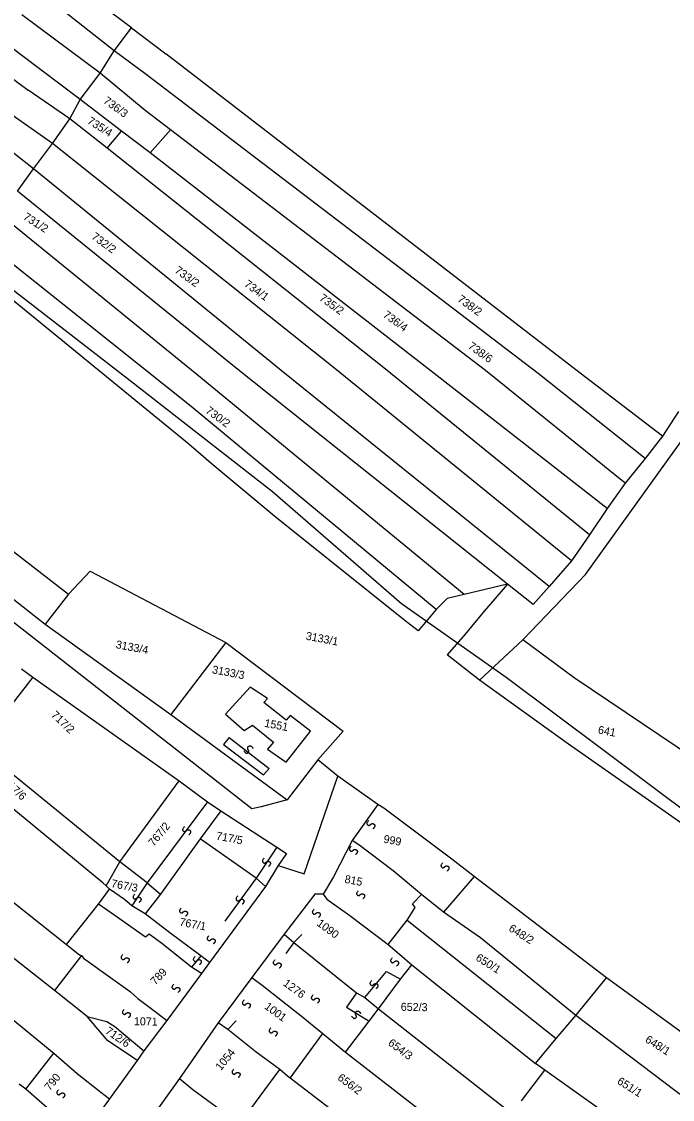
# Model space of a CAD drawing. Extents: x -581999 to -572728, y -1219553 to -1212032.
# Drawn here: x -577691.9 to -577529.2, y -1214814.1 to -1214544.8 of the extents above; entities that cross this region are included whole.
import ezdxf

# ---------------------------------------------------------------- set-up
doc = ezdxf.new("R2010")
doc.units = 0
for name, color, linetype in [('Vrstva 1', 7, 'Continuous'), ('Vrstva 2', 7, 'Continuous'), ('Vrstva 4', 7, 'Continuous'), ('Vrstva 6', 7, 'Continuous'), ('Vrstva 63', 7, 'Continuous')]:
    doc.layers.add(name, color=color, linetype=linetype)

msp = doc.modelspace()

# ---------------------------------------------------------------- linework, layer by layer
at = {"layer": 'Vrstva 1'}
for p, q in [((-577670.52, -1214576.417), (-577666.943, -1214572.148)), ((-577659.788, -1214577.612), (-577654.678, -1214571.806)), ((-577570.401, -1214685.384), (-577637.831, -1214631.7)), ((-577581.241, -1214687.954), (-577648.09, -1214633.013)), ((-577588.268, -1214691.703), (-577649.503, -1214641.002)), ((-577596.47, -1214694.225), (-577628.644, -1214668.451)), ((-577570.401, -1214685.384), (-577576.254, -1214692.158)), ((-577563.988, -1214690.489), (-577570.401, -1214685.384)), ((-577560.027, -1214685.925), (-577563.988, -1214690.489)), ((-577585.548, -1214688.977), (-577588.268, -1214691.703)), ((-577588.268, -1214691.703), (-577592.801, -1214697.043)), ((-577576.254, -1214692.158), (-577581.014, -1214697.839)), ((-577592.801, -1214697.043), (-577596.47, -1214694.225)), ((-577581.014, -1214697.839), (-577585.548, -1214703.065)), ((-577640.848, -1214699.921), (-577654.641, -1214717.954)), ((-577577.468, -1214709.362), (-577585.548, -1214703.065)), ((-577602.862, -1214740.427), (-577609.295, -1214749.455)), ((-577609.295, -1214749.455), (-577613.926, -1214758.483)), ((-577607.627, -1214750.552), (-577609.295, -1214749.455)), ((-577660.529, -1214760.031), (-577657.2, -1214762.813)), ((-577515.871, -1214821.604), (-577553.393, -1214793.129))]:
    msp.add_line(p, q, dxfattribs=at)
for points in [[(-577691.898, -1214553.29), (-577803.409, -1214468.543)], [(-577811.723, -1214471.875), (-577690.317, -1214561.946)], [(-577668.805, -1214552.092), (-577691.822, -1214533.865)], [(-577664.441, -1214546.324), (-577680.573, -1214534.167)], [(-577672.289, -1214557.707), (-577691.858, -1214543.078)], [(-577668.805, -1214552.092), (-577664.441, -1214546.324)], [(-577664.441, -1214546.324), (-577655.83, -1214552.859)], [(-577677.248, -1214564.27), (-577691.898, -1214553.29)], [(-577672.289, -1214557.707), (-577668.805, -1214552.092)], [(-577660.784, -1214558.021), (-577668.805, -1214552.092)], [(-577552.295, -1214632.621), (-577655.83, -1214552.859)], [(-577688.959, -1214581.583), (-577718.278, -1214558.503)], [(-577677.248, -1214564.27), (-577672.289, -1214557.707)], [(-577661.018, -1214567.027), (-577672.289, -1214557.707)], [(-577562.738, -1214632.734), (-577660.784, -1214558.021)], [(-577650.134, -1214650.396), (-577757.585, -1214562.563)], [(-577684.199, -1214575.219), (-577702.752, -1214562.237)], [(-577679.833, -1214569.052), (-577690.317, -1214561.946)], [(-577679.833, -1214569.052), (-577677.248, -1214564.27)], [(-577588.749, -1214632.714), (-577659.788, -1214577.612), (-577666.943, -1214572.148), (-577677.248, -1214564.27)], [(-577575.936, -1214632.022), (-577654.678, -1214571.806), (-577661.018, -1214567.027)], [(-577684.199, -1214575.219), (-577679.833, -1214569.052)], [(-577600.965, -1214631.61), (-577670.52, -1214576.417), (-577679.833, -1214569.052)], [(-577688.959, -1214581.583), (-577684.199, -1214575.219)], [(-577613.58, -1214631.504), (-577684.199, -1214575.219)], [(-577692.928, -1214587.153), (-577688.959, -1214581.583)], [(-577626.988, -1214631.991), (-577688.959, -1214581.583)], [(-577637.831, -1214631.7), (-577692.928, -1214587.153)], [(-577648.09, -1214633.013), (-577697.095, -1214593.122)], [(-577649.503, -1214641.002), (-577701.855, -1214599.286)], [(-577554.482, -1214679.576), (-577613.58, -1214631.504)], [(-577549.922, -1214673.019), (-577600.965, -1214631.61)], [(-577631.991, -1214741.032), (-577634.339, -1214741.551), (-577714.436, -1214678.933), (-577775.891, -1214632.778)], [(-577560.027, -1214685.925), (-577626.988, -1214631.991)], [(-577545.558, -1214666.46), (-577588.749, -1214632.714)], [(-577540.998, -1214660.102), (-577575.936, -1214632.022)], [(-577566.588, -1214699.26), (-577550.953, -1214683.002), (-577514.672, -1214632.54)], [(-577536.045, -1214653.947), (-577562.738, -1214632.734)], [(-577531.686, -1214648.387), (-577552.295, -1214632.621)], [(-577527.717, -1214642.224), (-577531.686, -1214648.387)], [(-577644.639, -1214655.116), (-577650.134, -1214650.396)], [(-577531.686, -1214648.387), (-577536.045, -1214653.947)], [(-577628.644, -1214668.451), (-577644.639, -1214655.116)], [(-577536.045, -1214653.947), (-577540.998, -1214660.102)], [(-577540.998, -1214660.102), (-577545.558, -1214666.46)], [(-577545.558, -1214666.46), (-577549.922, -1214673.019)], [(-577549.922, -1214673.019), (-577554.482, -1214679.576)], [(-577554.482, -1214679.576), (-577560.027, -1214685.925)], [(-577680.179, -1214687.879), (-577674.78, -1214682.14), (-577640.848, -1214699.921), (-577611.531, -1214722.118), (-577617.879, -1214729.244)], [(-577570.401, -1214685.384), (-577581.241, -1214687.954), (-577585.548, -1214688.977)], [(-577680.179, -1214687.879), (-577686.024, -1214695.333)], [(-577686.024, -1214695.333), (-577654.641, -1214717.954), (-577625.534, -1214739.291)], [(-577577.468, -1214709.362), (-577566.588, -1214699.26)], [(-577553.766, -1214708.8), (-577566.588, -1214699.26)], [(-577691.97, -1214706.552), (-577689.107, -1214708.631)], [(-577689.107, -1214708.631), (-577652.569, -1214734.552)], [(-577443.209, -1214803.732), (-577555.221, -1214725.368), (-577577.468, -1214709.362)], [(-577437.811, -1214786.816), (-577553.766, -1214708.8)], [(-577634.744, -1214711.087), (-577640.984, -1214717.905), (-577636.296, -1214721.95), (-577634.219, -1214720.63), (-577628.969, -1214724.87), (-577630.481, -1214726.574), (-577625.79, -1214729.854), (-577619.735, -1214722.082), (-577624.8, -1214718.226), (-577625.747, -1214719.372), (-577631.4, -1214714.962), (-577630.427, -1214713.984), (-577634.744, -1214711.087)], [(-577667.372, -1214754.76), (-577702.712, -1214726.052)], [(-577670.759, -1214760.798), (-577671.614, -1214760.013), (-577706.69, -1214731.204)], [(-577617.879, -1214729.244), (-577625.534, -1214739.291)], [(-577612.872, -1214733.36), (-577617.879, -1214729.244)], [(-577627.757, -1214755.657), (-577621.304, -1214757.745), (-577612.872, -1214733.36)], [(-577601.381, -1214741.367), (-577602.862, -1214740.427), (-577612.872, -1214733.36)], [(-577667.372, -1214754.76), (-577652.569, -1214734.552)], [(-577652.569, -1214734.552), (-577645.456, -1214739.736)], [(-577625.534, -1214739.291), (-577631.991, -1214741.032)], [(-577642.085, -1214742.015), (-577647.261, -1214749.052)], [(-577645.456, -1214739.736), (-577642.085, -1214742.015)], [(-577642.085, -1214742.015), (-577628.128, -1214751.096)], [(-577584.347, -1214754.125), (-577601.381, -1214741.367)], [(-577720.599, -1214743.762), (-577680.664, -1214775.408)], [(-577647.261, -1214749.052), (-577657.2, -1214762.813), (-577660.988, -1214767.785)], [(-577633.306, -1214758.865), (-577647.261, -1214749.052)], [(-577683.655, -1214786.955), (-577727.473, -1214752.486)], [(-577628.128, -1214751.096), (-577625.697, -1214752.671)], [(-577625.697, -1214752.671), (-577627.757, -1214755.657)], [(-577599.014, -1214757.022), (-577607.627, -1214750.552)], [(-577670.759, -1214760.798), (-577667.372, -1214754.76)], [(-577660.529, -1214760.031), (-577667.372, -1214754.76)], [(-577627.757, -1214755.657), (-577630.962, -1214760.92)], [(-577578.749, -1214758.393), (-577584.347, -1214754.125)], [(-577613.926, -1214758.483), (-577616.515, -1214762.83)], [(-577591.952, -1214762.918), (-577599.014, -1214757.022)], [(-577578.749, -1214758.393), (-577586.433, -1214767.341)], [(-577545.717, -1214783.726), (-577578.749, -1214758.393)], [(-577669.904, -1214761.582), (-577670.759, -1214760.798)], [(-577630.962, -1214760.92), (-577644.946, -1214779.941)], [(-577630.962, -1214760.92), (-577633.306, -1214758.865)], [(-577734.351, -1214761.263), (-577683.898, -1214802.605)], [(-577672.719, -1214765.351), (-577669.904, -1214761.582)], [(-577666.211, -1214764.174), (-577669.904, -1214761.582)], [(-577616.515, -1214762.83), (-577618.62, -1214762.813), (-577626.308, -1214772.863)], [(-577616.515, -1214762.83), (-577615.609, -1214764.055)], [(-577594.165, -1214765.294), (-577591.952, -1214762.918)], [(-577586.433, -1214767.341), (-577591.952, -1214762.918)], [(-577680.664, -1214775.408), (-577672.719, -1214765.351)], [(-577668.846, -1214768.036), (-577672.719, -1214765.351)], [(-577664.321, -1214765.745), (-577666.211, -1214764.174)], [(-577660.988, -1214767.785), (-577664.321, -1214765.745)], [(-577615.609, -1214764.055), (-577609.866, -1214768.143)], [(-577595.512, -1214769.326), (-577593.504, -1214766.197), (-577594.165, -1214765.294)], [(-577660.921, -1214773.59), (-577668.846, -1214768.036)], [(-577654.866, -1214772.501), (-577660.988, -1214767.785)], [(-577609.866, -1214768.143), (-577600.26, -1214775.405)], [(-577553.393, -1214793.129), (-577577.221, -1214773.748), (-577586.433, -1214767.341)], [(-577600.26, -1214775.405), (-577595.512, -1214769.326)], [(-577595.512, -1214769.326), (-577558.285, -1214798.909)], [(-577656.863, -1214775.177), (-577660.015, -1214772.865), (-577660.921, -1214773.59)], [(-577647.124, -1214778.236), (-577654.866, -1214772.501)], [(-577626.308, -1214772.863), (-577634.388, -1214783.632)], [(-577626.308, -1214772.863), (-577623.882, -1214774.944)], [(-577680.664, -1214775.408), (-577677.423, -1214777.996), (-577676.966, -1214778.171)], [(-577649.483, -1214781.092), (-577656.863, -1214775.177)], [(-577623.882, -1214774.944), (-577608.205, -1214787.531)], [(-577600.26, -1214775.405), (-577597.441, -1214777.801), (-577594.337, -1214780.504)], [(-577676.966, -1214778.171), (-577683.655, -1214786.955)], [(-577676.966, -1214778.171), (-577676.432, -1214778.827), (-577669.092, -1214784.053)], [(-577644.946, -1214779.941), (-577647.124, -1214778.236)], [(-577644.946, -1214779.941), (-577646.944, -1214782.672)], [(-577646.944, -1214782.672), (-577655.636, -1214794.441)], [(-577646.944, -1214782.672), (-577649.483, -1214781.092)], [(-577597.188, -1214784.103), (-577594.337, -1214780.504)], [(-577594.337, -1214780.504), (-577563.407, -1214805.156)], [(-577669.092, -1214784.053), (-577665.4, -1214786.736)], [(-577634.388, -1214783.632), (-577642.746, -1214795.023)], [(-577634.388, -1214783.632), (-577631.777, -1214785.626)], [(-577602.684, -1214791.504), (-577597.188, -1214784.103)], [(-577553.393, -1214793.129), (-577545.717, -1214783.726)], [(-577392.981, -1214894.666), (-577446.519, -1214855.132), (-577501.431, -1214815.879), (-577545.717, -1214783.726)], [(-577675.552, -1214793.424), (-577683.655, -1214786.955)], [(-577665.4, -1214786.736), (-577664.69, -1214787.284)], [(-577664.69, -1214787.284), (-577662.88, -1214788.952)], [(-577631.777, -1214785.626), (-577621.619, -1214793.565)], [(-577608.205, -1214787.531), (-577606.105, -1214788.67)], [(-577662.88, -1214788.952), (-577657.838, -1214792.652)], [(-577606.105, -1214788.67), (-577602.684, -1214791.504)], [(-577670.339, -1214799.504), (-577675.552, -1214793.424)], [(-577675.552, -1214793.424), (-577670.591, -1214794.653)], [(-577657.838, -1214792.652), (-577655.636, -1214794.441)], [(-577604.987, -1214794.598), (-577602.684, -1214791.504)], [(-577602.684, -1214791.504), (-577569.32, -1214817.641)], [(-577558.285, -1214798.909), (-577553.393, -1214793.129)], [(-577670.591, -1214794.653), (-577668.609, -1214795.948)], [(-577668.609, -1214795.948), (-577661.356, -1214801.993)], [(-577655.636, -1214794.441), (-577661.356, -1214801.993)], [(-577642.746, -1214795.023), (-577652.443, -1214808.875)], [(-577640.354, -1214796.663), (-577642.746, -1214795.023)], [(-577621.619, -1214793.565), (-577618.749, -1214795.946)], [(-577618.749, -1214795.946), (-577616.631, -1214797.653)], [(-577610.911, -1214802.293), (-577604.987, -1214794.598)], [(-577633.287, -1214802.332), (-577640.354, -1214796.663)], [(-577624.766, -1214808.82), (-577616.631, -1214797.653)], [(-577616.631, -1214797.653), (-577616.541, -1214797.759), (-577610.911, -1214802.293)], [(-577664.935, -1214803.115), (-577670.339, -1214799.504)], [(-577563.407, -1214805.156), (-577558.285, -1214798.909)], [(-577690.887, -1214811.561), (-577683.898, -1214802.605)], [(-577683.898, -1214802.605), (-577678.047, -1214807.682)], [(-577662.991, -1214804.451), (-577664.935, -1214803.115)], [(-577661.356, -1214801.993), (-577662.991, -1214804.451)], [(-577627.323, -1214806.643), (-577633.287, -1214802.332)], [(-577610.911, -1214802.293), (-577577.009, -1214828.694)], [(-577662.991, -1214804.451), (-577669.983, -1214814.006)], [(-577637.213, -1214820.018), (-577627.323, -1214806.643)], [(-577624.766, -1214808.82), (-577625.447, -1214808.342), (-577627.323, -1214806.643)], [(-577566.929, -1214814.48), (-577561.078, -1214806.816)], [(-577561.078, -1214806.816), (-577563.407, -1214805.156)], [(-577527.934, -1214830.82), (-577532.103, -1214827.51), (-577561.078, -1214806.816)], [(-577678.047, -1214807.682), (-577672.106, -1214812.303)], [(-577652.443, -1214808.875), (-577660.874, -1214820.637)], [(-577652.443, -1214808.875), (-577649.144, -1214811.619)], [(-577584.785, -1214839.458), (-577624.766, -1214808.82)], [(-577690.887, -1214811.561), (-577692.508, -1214810.36)], [(-577684.856, -1214816.822), (-577690.887, -1214811.561)], [(-577672.106, -1214812.303), (-577669.983, -1214814.006)], [(-577649.144, -1214811.619), (-577640.086, -1214818.2)], [(-577669.983, -1214814.006), (-577676.755, -1214823.38)]]:
    msp.add_lwpolyline(points, dxfattribs=at)
at = {"layer": 'Vrstva 4'}
for points in [[(-577724.162, -1214665.361), (-577718.492, -1214658.259), (-577680.179, -1214687.879)], [(-577724.162, -1214665.361), (-577686.024, -1214695.333)], [(-577689.107, -1214708.631), (-577702.712, -1214726.052)], [(-577640.067, -1214723.676), (-577641.483, -1214725.45), (-577631.477, -1214733.028), (-577630.061, -1214731.433)], [(-577640.067, -1214723.676), (-577630.061, -1214731.433)], [(-577645.456, -1214739.736), (-577660.529, -1214760.031)], [(-577628.128, -1214751.096), (-577633.306, -1214758.865)], [(-577660.529, -1214760.031), (-577664.321, -1214765.745)], [(-577633.306, -1214758.865), (-577641.092, -1214769.611)], [(-577621.86, -1214772.9), (-577623.882, -1214774.944)], [(-577623.882, -1214774.944), (-577625.831, -1214777.636)], [(-577647.124, -1214778.236), (-577649.483, -1214781.092)], [(-577606.105, -1214788.67), (-577600.658, -1214782.14)], [(-577600.658, -1214782.14), (-577597.188, -1214784.103)], [(-577608.205, -1214787.531), (-577610.652, -1214791.098), (-577604.987, -1214794.598)], [(-577638.319, -1214794.508), (-577640.354, -1214796.663)]]:
    msp.add_lwpolyline(points, dxfattribs=at)
at = {"layer": 'Vrstva 6'}
for points in [[(-577636.336, -1214727.051), (-577635.856, -1214727.758), (-577635.162, -1214727.447), (-577635.085, -1214727.047), (-577635.321, -1214726.702), (-577635.406, -1214726.37), (-577635.324, -1214726.08), (-577635.18, -1214725.9), (-577634.944, -1214725.772), (-577634.579, -1214725.808), (-577634.152, -1214726.247), (-577634.097, -1214726.42)], [(-577605.177, -1214744.443), (-577605.764, -1214745.065), (-577605.309, -1214745.674), (-577604.903, -1214745.662), (-577604.617, -1214745.357), (-577604.311, -1214745.203), (-577604.011, -1214745.219), (-577603.804, -1214745.321), (-577603.628, -1214745.524), (-577603.583, -1214745.888), (-577603.918, -1214746.4), (-577604.076, -1214746.492)], [(-577651.235, -1214745.991), (-577651.822, -1214746.613), (-577651.367, -1214747.222), (-577650.961, -1214747.21), (-577650.675, -1214746.905), (-577650.369, -1214746.751), (-577650.069, -1214746.767), (-577649.862, -1214746.869), (-577649.686, -1214747.072), (-577649.641, -1214747.436), (-577649.976, -1214747.948), (-577650.134, -1214748.04)], [(-577609.551, -1214750.892), (-577610.138, -1214751.514), (-577609.683, -1214752.123), (-577609.277, -1214752.111), (-577608.991, -1214751.806), (-577608.685, -1214751.652), (-577608.385, -1214751.668), (-577608.178, -1214751.77), (-577608.002, -1214751.973), (-577607.957, -1214752.337), (-577608.292, -1214752.849), (-577608.45, -1214752.941)], [(-577631.292, -1214753.866), (-577631.879, -1214754.488), (-577631.424, -1214755.097), (-577631.018, -1214755.085), (-577630.732, -1214754.78), (-577630.426, -1214754.626), (-577630.126, -1214754.642), (-577629.919, -1214754.744), (-577629.743, -1214754.947), (-577629.698, -1214755.311), (-577630.033, -1214755.823), (-577630.191, -1214755.915)], [(-577586.651, -1214755.019), (-577587.238, -1214755.641), (-577586.783, -1214756.25), (-577586.377, -1214756.238), (-577586.091, -1214755.933), (-577585.785, -1214755.779), (-577585.485, -1214755.795), (-577585.278, -1214755.897), (-577585.102, -1214756.1), (-577585.057, -1214756.464), (-577585.392, -1214756.976), (-577585.55, -1214757.068)], [(-577663.641, -1214762.844), (-577664.228, -1214763.466), (-577663.773, -1214764.075), (-577663.367, -1214764.063), (-577663.081, -1214763.758), (-577662.775, -1214763.604), (-577662.475, -1214763.62), (-577662.268, -1214763.722), (-577662.092, -1214763.925), (-577662.047, -1214764.289), (-577662.382, -1214764.801), (-577662.54, -1214764.893)], [(-577637.887, -1214763.316), (-577638.474, -1214763.938), (-577638.019, -1214764.547), (-577637.613, -1214764.535), (-577637.327, -1214764.23), (-577637.021, -1214764.076), (-577636.721, -1214764.092), (-577636.514, -1214764.194), (-577636.338, -1214764.397), (-577636.293, -1214764.761), (-577636.628, -1214765.273), (-577636.786, -1214765.365)], [(-577607.75, -1214761.983), (-577608.337, -1214762.605), (-577607.882, -1214763.214), (-577607.476, -1214763.202), (-577607.19, -1214762.897), (-577606.884, -1214762.743), (-577606.584, -1214762.759), (-577606.377, -1214762.861), (-577606.201, -1214763.064), (-577606.156, -1214763.428), (-577606.491, -1214763.94), (-577606.649, -1214764.032)], [(-577652.02, -1214766.309), (-577652.607, -1214766.931), (-577652.152, -1214767.54), (-577651.746, -1214767.528), (-577651.46, -1214767.223), (-577651.154, -1214767.069), (-577650.854, -1214767.085), (-577650.647, -1214767.187), (-577650.471, -1214767.39), (-577650.426, -1214767.754), (-577650.761, -1214768.266), (-577650.919, -1214768.358)], [(-577618.814, -1214766.626), (-577619.401, -1214767.248), (-577618.946, -1214767.857), (-577618.54, -1214767.845), (-577618.254, -1214767.54), (-577617.948, -1214767.386), (-577617.648, -1214767.402), (-577617.441, -1214767.504), (-577617.265, -1214767.707), (-577617.22, -1214768.071), (-577617.555, -1214768.583), (-577617.713, -1214768.675)], [(-577645.111, -1214773.239), (-577645.698, -1214773.861), (-577645.243, -1214774.47), (-577644.837, -1214774.458), (-577644.551, -1214774.153), (-577644.245, -1214773.999), (-577643.945, -1214774.015), (-577643.738, -1214774.117), (-577643.562, -1214774.32), (-577643.517, -1214774.684), (-577643.852, -1214775.196), (-577644.01, -1214775.288)], [(-577666.625, -1214777.964), (-577667.212, -1214778.586), (-577666.757, -1214779.195), (-577666.351, -1214779.183), (-577666.065, -1214778.878), (-577665.759, -1214778.724), (-577665.459, -1214778.74), (-577665.252, -1214778.842), (-577665.076, -1214779.045), (-577665.031, -1214779.409), (-577665.366, -1214779.921), (-577665.524, -1214780.013)], [(-577648.566, -1214778.437), (-577649.153, -1214779.059), (-577648.698, -1214779.668), (-577648.292, -1214779.656), (-577648.006, -1214779.351), (-577647.7, -1214779.197), (-577647.4, -1214779.213), (-577647.193, -1214779.315), (-577647.017, -1214779.518), (-577646.972, -1214779.882), (-577647.307, -1214780.394), (-577647.465, -1214780.486)], [(-577628.592, -1214779.265), (-577629.179, -1214779.887), (-577628.724, -1214780.496), (-577628.318, -1214780.484), (-577628.032, -1214780.179), (-577627.726, -1214780.025), (-577627.426, -1214780.041), (-577627.219, -1214780.143), (-577627.043, -1214780.346), (-577626.998, -1214780.71), (-577627.333, -1214781.222), (-577627.491, -1214781.314)], [(-577599.259, -1214778.749), (-577599.846, -1214779.371), (-577599.391, -1214779.98), (-577598.985, -1214779.968), (-577598.699, -1214779.663), (-577598.393, -1214779.509), (-577598.093, -1214779.525), (-577597.886, -1214779.627), (-577597.71, -1214779.83), (-577597.665, -1214780.194), (-577598, -1214780.706), (-577598.158, -1214780.798)], [(-577653.905, -1214785.367), (-577654.492, -1214785.989), (-577654.037, -1214786.598), (-577653.631, -1214786.586), (-577653.345, -1214786.281), (-577653.039, -1214786.127), (-577652.739, -1214786.143), (-577652.532, -1214786.245), (-577652.356, -1214786.448), (-577652.311, -1214786.812), (-577652.646, -1214787.324), (-577652.804, -1214787.416)], [(-577604.405, -1214784.424), (-577604.992, -1214785.046), (-577604.537, -1214785.655), (-577604.131, -1214785.643), (-577603.845, -1214785.338), (-577603.539, -1214785.184), (-577603.239, -1214785.2), (-577603.032, -1214785.302), (-577602.856, -1214785.505), (-577602.811, -1214785.869), (-577603.146, -1214786.381), (-577603.304, -1214786.473)], [(-577619.072, -1214788.035), (-577619.659, -1214788.657), (-577619.204, -1214789.266), (-577618.798, -1214789.254), (-577618.512, -1214788.949), (-577618.206, -1214788.795), (-577617.906, -1214788.811), (-577617.699, -1214788.913), (-577617.523, -1214789.116), (-577617.478, -1214789.48), (-577617.813, -1214789.992), (-577617.971, -1214790.084)], [(-577636.311, -1214789.325), (-577636.898, -1214789.947), (-577636.443, -1214790.556), (-577636.037, -1214790.544), (-577635.751, -1214790.239), (-577635.445, -1214790.085), (-577635.145, -1214790.101), (-577634.938, -1214790.203), (-577634.762, -1214790.406), (-577634.717, -1214790.77), (-577635.052, -1214791.282), (-577635.21, -1214791.374)], [(-577666.31, -1214791.667), (-577666.897, -1214792.289), (-577666.442, -1214792.898), (-577666.036, -1214792.886), (-577665.75, -1214792.581), (-577665.444, -1214792.427), (-577665.144, -1214792.443), (-577664.937, -1214792.545), (-577664.761, -1214792.748), (-577664.716, -1214793.112), (-577665.051, -1214793.624), (-577665.209, -1214793.716)], [(-577609.422, -1214793.32), (-577608.942, -1214794.027), (-577608.248, -1214793.716), (-577608.171, -1214793.316), (-577608.407, -1214792.971), (-577608.492, -1214792.639), (-577608.41, -1214792.349), (-577608.266, -1214792.169), (-577608.03, -1214792.041), (-577607.665, -1214792.077), (-577607.238, -1214792.516), (-577607.183, -1214792.689)], [(-577629.621, -1214796.289), (-577630.208, -1214796.911), (-577629.753, -1214797.52), (-577629.347, -1214797.508), (-577629.061, -1214797.203), (-577628.755, -1214797.049), (-577628.455, -1214797.065), (-577628.248, -1214797.167), (-577628.072, -1214797.37), (-577628.027, -1214797.734), (-577628.362, -1214798.246), (-577628.52, -1214798.338)], [(-577638.884, -1214806.607), (-577639.471, -1214807.229), (-577639.016, -1214807.838), (-577638.61, -1214807.826), (-577638.324, -1214807.521), (-577638.018, -1214807.367), (-577637.718, -1214807.383), (-577637.511, -1214807.485), (-577637.335, -1214807.688), (-577637.29, -1214808.052), (-577637.625, -1214808.564), (-577637.783, -1214808.656)], [(-577682.714, -1214811.748), (-577683.301, -1214812.37), (-577682.846, -1214812.979), (-577682.44, -1214812.967), (-577682.154, -1214812.662), (-577681.848, -1214812.508), (-577681.548, -1214812.524), (-577681.341, -1214812.626), (-577681.165, -1214812.829), (-577681.12, -1214813.193), (-577681.455, -1214813.705), (-577681.613, -1214813.797)]]:
    msp.add_open_spline(points, degree=2, dxfattribs=at)
at = {"layer": 'Vrstva 63'}
for p, q in [((-577665.568, -1214634.018), (-577712.533, -1214597.644)), ((-577629.214, -1214662.33), (-577665.568, -1214634.018)), ((-577596.927, -1214690.291), (-577629.214, -1214662.33)), ((-577570.753, -1214708.731), (-577596.927, -1214690.291)), ((-577499.295, -1214762.226), (-577570.753, -1214708.731))]:
    msp.add_line(p, q, dxfattribs=at)

# ---------------------------------------------------------------- texts
at = {"layer": 'Vrstva 2'}
for s, rotation, p in [('736/3', 324.12454, (-577671.657, -1214564.967)), ('735/4', 327.58282, (-577675.688, -1214570.092)), ('731/2', 327.58282, (-577691.705, -1214594.067)), ('732/2', 324.12454, (-577674.626, -1214598.915)), ('733/2', 324.12454, (-577653.823, -1214607.34)), ('734/1', 324.12454, (-577636.447, -1214610.777)), ('735/2', 324.12454, (-577617.685, -1214614.271)), ('738/2', 324.12454, (-577583.135, -1214614.549)), ('736/4', 324.12454, (-577601.736, -1214618.462)), ('738/6', 324.12454, (-577580.477, -1214626.267)), ('730/2', 324.12454, (-577646.111, -1214642.412)), ('3133/1', 349.25111, (-577620.983, -1214699.212)), ('3133/4', 349.25111, (-577668.496, -1214701.341)), ('3133/3', 349.25111, (-577644.413, -1214707.622)), ('717/2', 316.59192, (-577684.696, -1214718.263)), ('1551', 349.25111, (-577631.329, -1214720.994)), ('641', 349.25111, (-577547.948, -1214722.677)), ('717/6', 316.59192, (-577696.743, -1214734.949)), ('767/2', 50.58433, (-577658.885, -1214751.059)), ('717/5', 349.25111, (-577643.408, -1214749.176)), ('999', 349.25111, (-577601.573, -1214749.953)), ('815', 349.25111, (-577611.286, -1214759.98)), ('767/3', 349.25111, (-577669.653, -1214761.074)), ('767/1', 349.25111, (-577652.574, -1214770.686)), ('1090', 323.42903, (-577618.296, -1214770.518)), ('648/2', 327.82777, (-577570.336, -1214771.894)), ('650/1', 327.82777, (-577578.574, -1214779.226)), ('789', 46.17912, (-577658.498, -1214785.694)), ('1276', 323.42903, (-577626.712, -1214785.485)), ('1001', 323.42903, (-577631.384, -1214791.284)), ('652/3', 359.00608, (-577597.135, -1214791.983)), ('712/6', 325.56556, (-577671.188, -1214797.481)), ('1071', 359.00608, (-577663.853, -1214795.598)), ('648/1', 327.82777, (-577536.206, -1214799.662)), ('1054', 51.17731, (-577642.1, -1214807.087)), ('654/3', 323.42903, (-577600.479, -1214800.394)), ('790', 51.17731, (-577684.835, -1214812.121)), ('656/2', 323.42903, (-577613.114, -1214809.094)), ('651/1', 327.82777, (-577543.215, -1214810.085))]:
    msp.add_text(s, height=2, rotation=rotation, dxfattribs=at).set_placement(p)

doc.saveas('drawing.dxf')
